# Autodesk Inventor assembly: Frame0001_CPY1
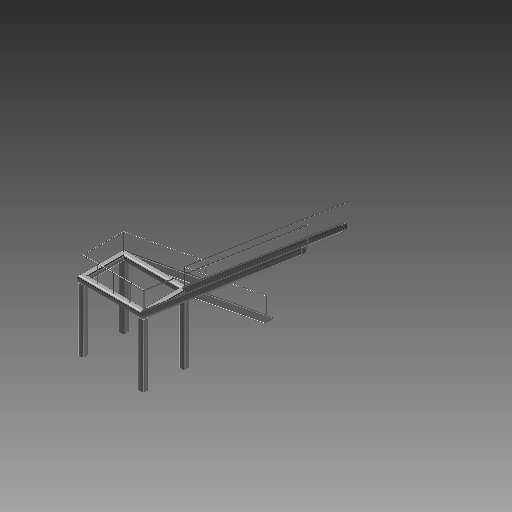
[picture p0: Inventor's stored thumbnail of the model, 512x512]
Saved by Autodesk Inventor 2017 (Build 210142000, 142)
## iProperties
Created: 2017-11
Part Number: Frame0001_CPY1
Document SubType Name: Assembly
Designer: iusti
Mass: 7.38505e+06 g
Surface Area: 1.18279e+06 cm^2
Volume: 940770 cm^3
Density: 7.85 g/cm^3
Author: iusti
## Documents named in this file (55)
- C:\Users\iusti\Desktop\pasarela\Schelet pasarela\Frame\Frame0001_CPY1.iam
- C:\Users\iusti\Desktop\pasarela\Schelet pasarela\Frame\DIN 150 x 150 x 16 00000100_CPY1.ipt
- DIN 150 x 150 x 16 00000100.ipt
- C:\Users\iusti\Desktop\pasarela\Schelet pasarela\Frame\DIN 150 x 150 x 16 00000101_CPY1.ipt
- DIN 150 x 150 x 16 00000101.ipt
- C:\Users\iusti\Desktop\pasarela\Schelet pasarela\Frame\DIN 150 x 150 x 16 00000102_CPY1.ipt
- DIN 150 x 150 x 16 00000102.ipt
- C:\Users\iusti\Desktop\pasarela\Schelet pasarela\Frame\DIN 150 x 150 x 16 00000103_CPY1.ipt
- DIN 150 x 150 x 16 00000103.ipt
- C:\Users\iusti\Desktop\pasarela\Schelet pasarela\Frame\DIN 150 x 150 x 16 00000104_CPY1.ipt
- DIN 150 x 150 x 16 00000104.ipt
- C:\Users\iusti\Desktop\pasarela\Schelet pasarela\Frame\DIN 150 x 150 x 16 00000105_CPY1.ipt
- DIN 150 x 150 x 16 00000105.ipt
- C:\Users\iusti\Desktop\pasarela\Schelet pasarela\Frame\DIN 150 x 150 x 16 00000106_CPY1.ipt
- DIN 150 x 150 x 16 00000106.ipt
- C:\Users\iusti\Desktop\pasarela\Schelet pasarela\Frame\DIN 150 x 150 x 16 00000107_CPY1.ipt
- DIN 150 x 150 x 16 00000107.ipt
- C:\Users\iusti\Desktop\pasarela\Schelet pasarela\Frame\DIN 150 x 150 x 16 00000108_CPY1.ipt
- DIN 150 x 150 x 16 00000108.ipt
- C:\Users\iusti\Desktop\pasarela\Schelet pasarela\Frame\DIN 150 x 150 x 16 00000109_CPY1.ipt
- DIN 150 x 150 x 16 00000109.ipt
- C:\Users\iusti\Desktop\pasarela\Schelet pasarela\Frame\DIN 150 x 150 x 16 00000116_CPY.ipt
- DIN 150 x 150 x 16 00000116.ipt
- C:\Users\iusti\Desktop\pasarela\Schelet pasarela\Frame\DIN 150 x 150 x 16 00000117_CPY.ipt
- DIN 150 x 150 x 16 00000117.ipt
- C:\Users\iusti\Desktop\pasarela\Schelet pasarela\Frame\DIN 21.3 x 2.3 00000121_CPY.ipt
- DIN 21.3 x 2.3 00000121.ipt
- C:\Users\iusti\Desktop\pasarela\Schelet pasarela\Frame\DIN 21.3 x 2.3 00000122_CPY.ipt
- DIN 21.3 x 2.3 00000122.ipt
- C:\Users\iusti\Desktop\pasarela\Schelet pasarela\Frame\DIN 21.3 x 2.3 00000123_CPY.ipt
- DIN 21.3 x 2.3 00000123.ipt
- C:\Users\iusti\Desktop\pasarela\Schelet pasarela\Frame\DIN 21.3 x 2.3 00000124_CPY.ipt
- DIN 21.3 x 2.3 00000124.ipt
- C:\Users\iusti\Desktop\pasarela\Schelet pasarela\Frame\DIN 21.3 x 2.3 00000125_CPY.ipt
- DIN 21.3 x 2.3 00000125.ipt
- C:\Users\iusti\Desktop\pasarela\Schelet pasarela\Frame\DIN 21.3 x 2.3 00000126_CPY.ipt
- DIN 21.3 x 2.3 00000126.ipt
- C:\Users\iusti\Desktop\pasarela\Schelet pasarela\Frame\DIN 21.3 x 2.3 00000127_CPY.ipt
- DIN 21.3 x 2.3 00000127.ipt
- C:\Users\iusti\Desktop\pasarela\Schelet pasarela\Frame\DIN 21.3 x 2.3 00000128_CPY.ipt
- DIN 21.3 x 2.3 00000128.ipt
- C:\Users\iusti\Desktop\pasarela\Schelet pasarela\Frame\DIN 21.3 x 2.3 00000158_CPY.ipt
- DIN 21.3 x 2.3 00000158.ipt
- C:\Users\iusti\Desktop\pasarela\Schelet pasarela\Frame\DIN 21.3 x 2.3 00000159_CPY.ipt
- DIN 21.3 x 2.3 00000159.ipt
- C:\Users\iusti\Desktop\pasarela\Schelet pasarela\Frame\DIN 21.3 x 2.3 00000160_CPY.ipt
- DIN 21.3 x 2.3 00000160.ipt
- C:\Users\iusti\Desktop\pasarela\Schelet pasarela\Frame\DIN 21.3 x 2.3 00000161_CPY.ipt
- DIN 21.3 x 2.3 00000161.ipt
- C:\Users\iusti\Desktop\pasarela\Schelet pasarela\Frame\DIN 21.3 x 2.3 00000162_CPY.ipt
- DIN 21.3 x 2.3 00000162.ipt
- C:\Users\iusti\Desktop\pasarela\Schelet pasarela\Frame\DIN 21.3 x 2.3 00000163_CPY.ipt
- DIN 21.3 x 2.3 00000163.ipt
- C:\Users\iusti\Desktop\pasarela\Schelet pasarela\Frame\DIN 21.3 x 2.3 00000164_CPY.ipt
- DIN 21.3 x 2.3 00000164.ipt
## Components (27 placed, 27 different names)
1. DIN 150 x 150 x 16 00000100:1
2. DIN 150 x 150 x 16 00000101:1
3. DIN 150 x 150 x 16 00000102:1
4. DIN 150 x 150 x 16 00000103:1
5. DIN 150 x 150 x 16 00000104:1
6. DIN 150 x 150 x 16 00000105:1
7. DIN 150 x 150 x 16 00000106:1
8. DIN 150 x 150 x 16 00000107:1
9. DIN 150 x 150 x 16 00000108:1
10. DIN 150 x 150 x 16 00000109:1
11. DIN 150 x 150 x 16 00000116:1
12. DIN 150 x 150 x 16 00000117:1
13. DIN 21.3 x 2.3 00000121:1
14. DIN 21.3 x 2.3 00000122:1
15. DIN 21.3 x 2.3 00000123:1
16. DIN 21.3 x 2.3 00000124:1
17. DIN 21.3 x 2.3 00000125:1
18. DIN 21.3 x 2.3 00000126:1
19. DIN 21.3 x 2.3 00000127:1
20. DIN 21.3 x 2.3 00000128:1
21. DIN 21.3 x 2.3 00000158:1
22. DIN 21.3 x 2.3 00000159:1
23. DIN 21.3 x 2.3 00000160:1
24. DIN 21.3 x 2.3 00000161:1
25. DIN 21.3 x 2.3 00000162:1
26. DIN 21.3 x 2.3 00000163:1
27. DIN 21.3 x 2.3 00000164:1
